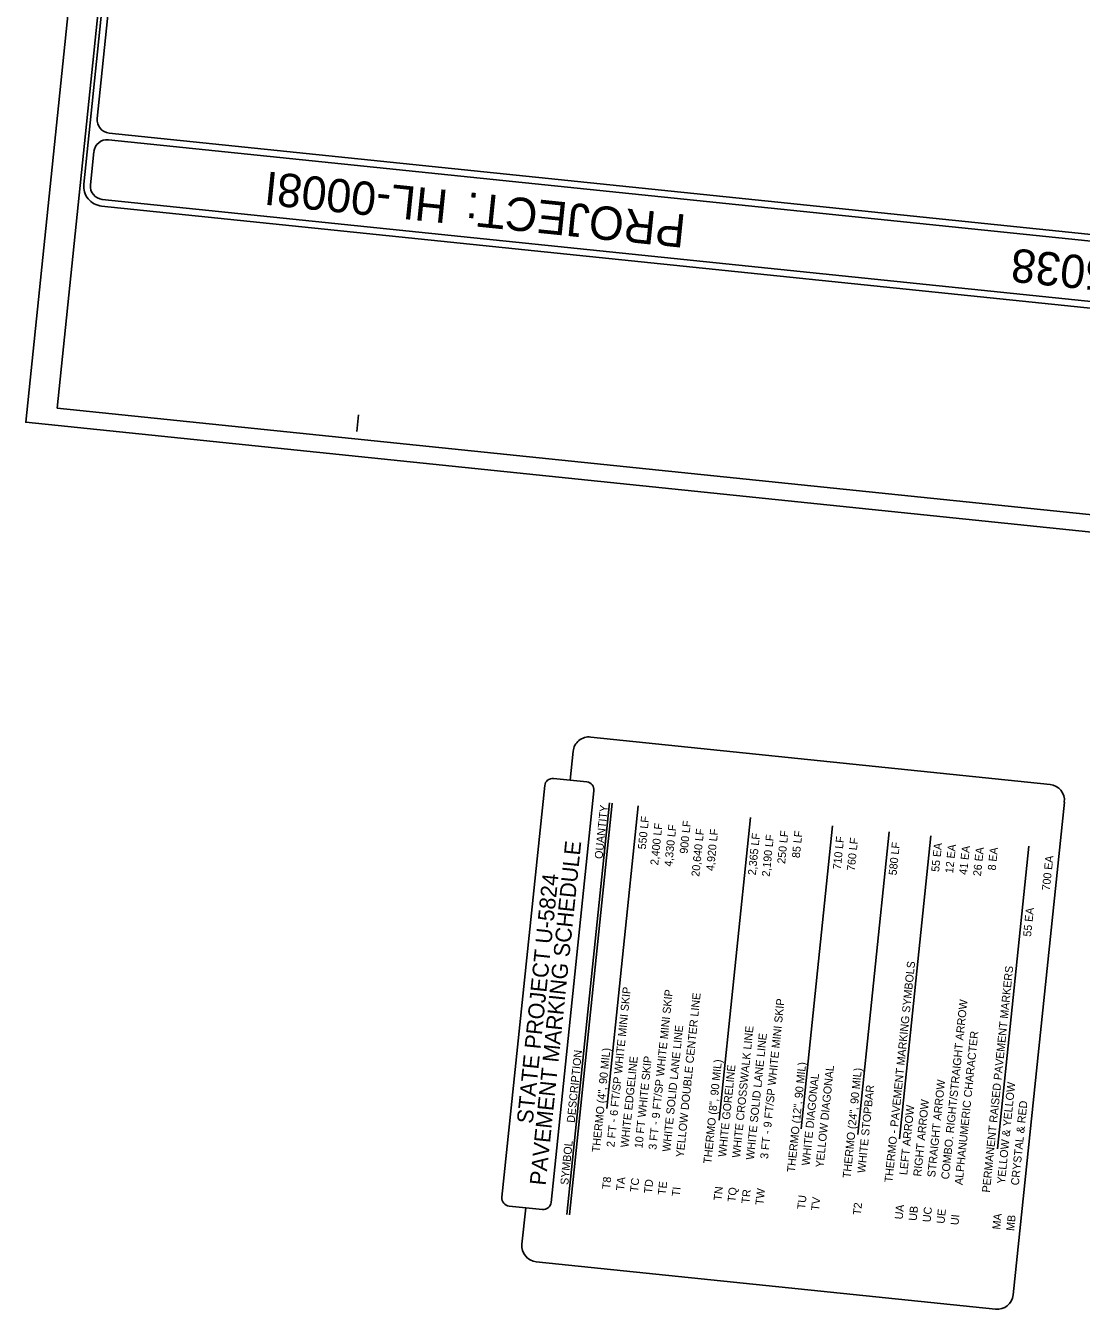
# Model space of a CAD drawing. Extents: x 2077770 to 2079037, y 247476 to 249877.
# Drawn here: x 2077770 to 2078561, y 247476 to 248438 of the extents above; entities that cross this region are included whole.
import ezdxf

# ---------------------------------------------------------------- set-up
doc = ezdxf.new("R2010")
doc.units = 0
for name, color, linetype in [('Default', 7, 'Continuous'), ('Prop DSN Text', 7, 'Continuous'), ('Sheet Plot Border Inside CELL', 7, 'Continuous'), ('Sheet Plot Border Outside CELL', 7, 'Continuous'), ('Sheet Title CELL', 7, 'Continuous')]:
    doc.layers.add(name, color=color, linetype=linetype)

msp = doc.modelspace()

# ---------------------------------------------------------------- linework, layer by layer
at = {"layer": 'Default'}
for p, q in [((2078175.8, 247547.14), (2078207.86, 247855.79)), ((2078177.79, 247546.94), (2078209.85, 247855.58)), ((2078205.8, 247626.49), (2078229.23, 247853.58)), ((2078290.15, 247617.79), (2078313.59, 247844.87)), ((2078351.57, 247611.45), (2078375.01, 247838.53)), ((2078394.05, 247607.06), (2078417.49, 247834.15)), ((2078425.14, 247603.85), (2078448.58, 247830.94)), ((2078498.72, 247596.26), (2078522.16, 247823.35))]:
    msp.add_line(p, q, dxfattribs=at)
at = {"layer": 'Sheet Plot Border Inside CELL'}
msp.add_lwpolyline([(2078843.53, 248043.45), (2079014.62, 249701.14), (2077965.1, 249809.47), (2077794, 248151.77)], close=True, dxfattribs=at)
at = {"layer": 'Sheet Plot Border Outside CELL'}
msp.add_lwpolyline([(2077943.23, 249816.25), (2077770.34, 248141.15), (2078864.51, 248028.21), (2079037.4, 249703.31)], close=True, dxfattribs=at)
at = {"layer": 'Sheet Title CELL'}
for p, q in [((2078847.53, 248253.15), (2077832.92, 248357.87)), ((2078847, 248248.17), (2077832.4, 248352.89)), ((2078018.43, 248134.14), (2078019.71, 248146.57)), ((2078193.78, 247905.13), (2078538.01, 247869.54)), ((2078180.61, 247894.43), (2078178.36, 247872.75)), ((2078127.23, 247560.05), (2078159.3, 247868.69)), ((2078165.88, 247874.05), (2078190.83, 247871.46)), ((2078196.18, 247864.87), (2078164.11, 247556.23)), ((2078510.32, 247486.8), (2078548.71, 247856.37)), ((2078132.58, 247553.47), (2078157.53, 247550.88)), ((2078142.22, 247524.87), (2078145.05, 247552.17)), ((2078152.91, 247511.69), (2078497.14, 247476.1))]:
    msp.add_line(p, q, dxfattribs=at)
for points in [[(2077964.81, 249781.85), (2077813.88, 248319.62)], [(2077969.78, 249781.34), (2077824, 248368.84)], [(2077821.43, 248343.98), (2077818.85, 248319.12)], [(2077827.26, 248303.16), (2078841.88, 248198.44)], [(2077827.77, 248308.14), (2078842.38, 248203.41)]]:
    msp.add_lwpolyline(points, dxfattribs=at)
for centre, radius, start, end in [((2077833.94, 248367.81), 10, 174.10721, 264.10721), ((2077831.38, 248342.95), 10, 84.10721, 174.07856), ((2077828.8, 248318.08), 15, 174.10672, 264.10721), ((2077828.8, 248318.09), 10, 174.07856, 264.10651), ((2078192.54, 247893.19), 12, 84.06941, 174.06941), ((2078165.26, 247868.07), 6, 84.06941, 174.06941), ((2078190.21, 247865.49), 6, 354.06941, 84.06941), ((2078536.77, 247857.61), 12, 354.06941, 84.06941), ((2078133.2, 247559.43), 6, 174.06941, 264.06941), ((2078158.15, 247556.85), 6, 264.06941, 354.06941), ((2078154.15, 247523.63), 12, 174.06941, 264.06941), ((2078498.38, 247488.04), 12, 264.06941, 354.06941)]:
    msp.add_arc(centre, radius, start, end, dxfattribs=at)

# ---------------------------------------------------------------- texts
at = {"layer": 'Default'}
for s, p in [('PAVEMENT MARKING SCHEDULE', (2078159.93, 247568.55)), ('STATE PROJECT U-5824', (2078150.27, 247614.86))]:
    msp.add_text(s, height=12, rotation=84.06941, dxfattribs=at).set_placement(p)
at = {"layer": 'Prop DSN Text'}
for s, p in [('QUANTITY', (2078202.62, 247813.49)), ('550 LF', (2078235.01, 247820.62)), ('2,400 LF', (2078244.34, 247808.8)), ('4,330 LF', (2078254.78, 247807.72)), ('900 LF', (2078266.33, 247817.39)), ('20,640 LF', (2078275.11, 247800.19)), ('4,920 LF', (2078286.11, 247804.49)), ('2,365 LF', (2078317.43, 247801.26)), ('2,190 LF', (2078327.88, 247800.18)), ('250 LF', (2078339.43, 247809.84)), ('85 LF', (2078350.42, 247814.14)), ('710 LF', (2078381.19, 247805.53)), ('760 LF', (2078391.63, 247804.45)), ('580 LF', (2078422.96, 247801.22)), ('55 EA', (2078454.88, 247803.78)), ('12 EA', (2078465.32, 247802.7)), ('41 EA', (2078475.76, 247801.62)), ('26 EA', (2078486.2, 247800.55)), ('8 EA', (2078497.2, 247804.84)), ('700 EA', (2078537.86, 247789.79)), ('             55 EA', (2078520.76, 247726.4)), ('            THERMO - PAVEMENT MARKING SYMBOLS', (2078417.08, 247544.3)), ('            PERMANENT RAISED PAVEMENT MARKERS', (2078490.17, 247536.76)), ('T8          2 FT - 6 FT/SP WHITE MINI SKIP', (2078208.25, 247565.86)), ('TD          3 FT - 9 FT/SP WHITE MINI SKIP', (2078239.57, 247562.62)), ('TI          YELLOW DOUBLE CENTER LINE', (2078260.46, 247560.47)), ('TW          3 FT - 9 FT/SP WHITE MINI SKIP', (2078323.1, 247554)), ('UE          COMBO. RIGHT/STRAIGHT ARROW', (2078458.84, 247539.99)), ('TE          WHITE SOLID LANE LINE', (2078250.01, 247561.55)), ('TQ          WHITE CROSSWALK LINE', (2078302.22, 247556.16)), ('UI          ALPHANUMERIC CHARACTER', (2078469.29, 247538.91)), ('TR          WHITE SOLID LANE LINE', (2078312.66, 247555.08)), ('SYMBOL      DESCRIPTION', (2078176.92, 247569.09)), ('            THERMO (4", 90 MIL)', (2078197.81, 247566.93)), ('TA          WHITE EDGELINE', (2078218.69, 247564.78)), ('TC          10 FT WHITE SKIP', (2078229.13, 247563.7)), ('            THERMO (8", 90 MIL)', (2078281.34, 247558.31)), ('TN          WHITE GORELINE', (2078291.78, 247557.24)), ('            THERMO (12", 90 MIL)', (2078343.99, 247551.85)), ('TV          YELLOW DIAGONAL', (2078364.87, 247549.69)), ('            THERMO (24", 90 MIL)', (2078385.75, 247547.54)), ('TU          WHITE DIAGONAL', (2078354.43, 247550.77)), ('UC          STRAIGHT ARROW', (2078448.4, 247541.07)), ('MA          YELLOW & YELLOW', (2078500.61, 247535.68)), ('T2          WHITE STOPBAR', (2078396.19, 247546.46)), ('UA          LEFT ARROW', (2078427.52, 247543.23)), ('UB          RIGHT ARROW', (2078437.96, 247542.15)), ('MB          CRYSTAL & RED', (2078511.05, 247534.6))]:
    msp.add_text(s, height=6, rotation=84.10721, dxfattribs=at).set_placement(p)
at = {"layer": 'Sheet Title CELL'}
for s, p in [('HL-0008I', (2078087.71, 248315.09)), ('PROJECT:', (2078265.97, 248296.7)), ('CONTRACT: C205038', (2078848.36, 248236.59))]:
    msp.add_text(s, height=25, rotation=174.10721, dxfattribs=at).set_placement(p)

doc.saveas('drawing.dxf')
